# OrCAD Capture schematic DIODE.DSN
size A
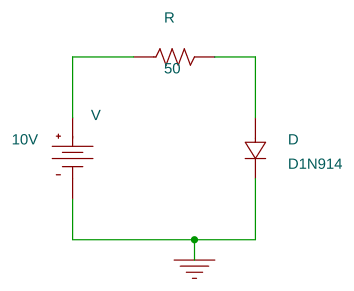
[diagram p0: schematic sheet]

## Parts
D  D1N914  [DO-35]
R  50  [AX/RC05]
V  VDC

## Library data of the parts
D = D1N914
R = R
V = VDC: DC: 10V

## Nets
0: D.2 V.1(-)
N00081: R.1 V.0(+)
N00087: D.1 R.2
